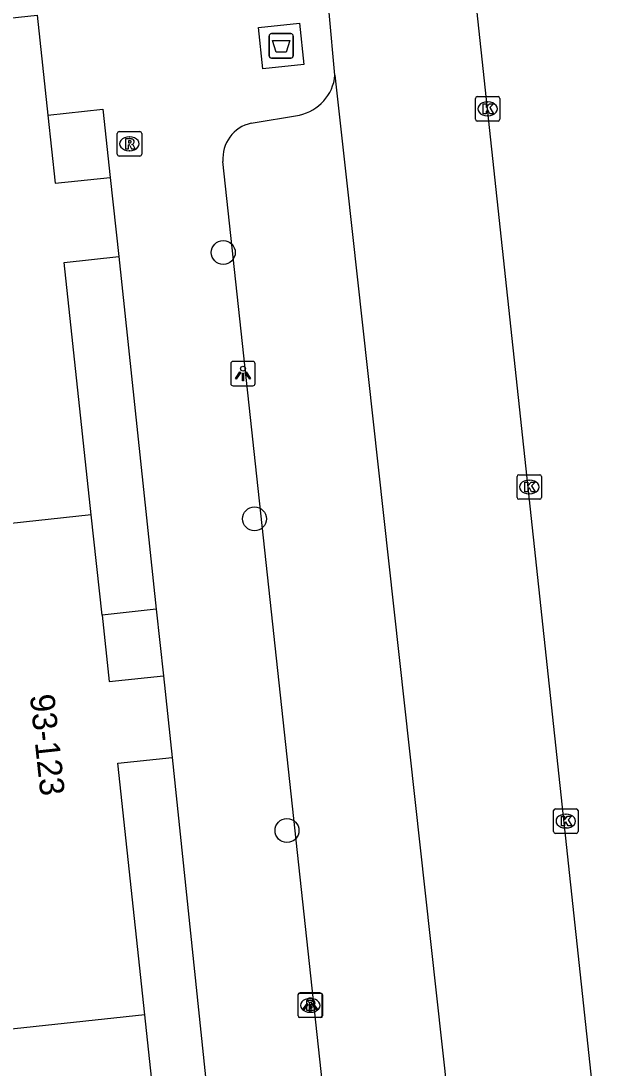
# Model space of a CAD drawing. Extents: x 161253 to 161848, y 384872 to 385383.
# Drawn here: x 161305.25 to 161328.98, y 385112.17 to 385154.91 of the extents above; entities that cross this region are included whole.
import ezdxf

# ---------------------------------------------------------------- set-up
doc = ezdxf.new("R2010")
doc.units = 0
for name, color, linetype in [('IMGEO_Afval_apart_plaats', 7, 'Continuous'), ('IMGEO_Boom', 7, 'Continuous'), ('IMGEO_Brandkraan', 7, 'Continuous'), ('IMGEO_Kolk', 7, 'Continuous'), ('IMGEO_Lichtpunt', 7, 'Continuous'), ('IMGEO_Pand', 7, 'Continuous'), ('IMGEO_Pand_nummerreeks', 7, 'Continuous'), ('IMGEO_Rijbaan_lokaal_open', 7, 'Continuous'), ('IMGEO_Rioolput', 7, 'Continuous'), ('IMGEO_Voetpad_gesloten', 7, 'Continuous'), ('IMGEO_Voetpad_open', 7, 'Continuous')]:
    doc.layers.add(name, color=color, linetype=linetype)

msp = doc.modelspace()

# ---------------------------------------------------------------- linework, layer by layer
at = {"layer": 'IMGEO_Afval_apart_plaats'}
for p, q in [((161315.384, 385153.496), (161315.384, 385154.296)), ((161315.384, 385154.296), (161315.384, 385153.496)), ((161315.484, 385154.396), (161316.274, 385154.396)), ((161316.274, 385154.396), (161315.484, 385154.396)), ((161316.374, 385154.296), (161316.374, 385153.496)), ((161316.374, 385153.496), (161316.374, 385154.296)), ((161316.274, 385153.396), (161315.484, 385153.396)), ((161315.484, 385153.396), (161316.274, 385153.396))]:
    msp.add_line(p, q, dxfattribs=at)
msp.add_lwpolyline([(161315.527, 385154.11), (161316.231, 385154.11), (161316.082, 385153.64), (161315.676, 385153.64), (161315.527, 385154.11)], dxfattribs=at)
for centre, start, end in [((161315.484, 385154.296), 90, 180), ((161315.484, 385154.296), 90, 180), ((161316.274, 385154.296), 0, 90), ((161316.274, 385154.296), 360, 90), ((161315.484, 385153.496), 180, 270), ((161315.484, 385153.496), 180, 270), ((161316.274, 385153.496), 270, 0), ((161316.274, 385153.496), 270, 0)]:
    msp.add_arc(centre, 0.1, start, end, dxfattribs=at)
at = {"layer": 'IMGEO_Boom'}
for centre in [(161313.513, 385145.462), (161314.788, 385134.591), (161316.115, 385121.867)]:
    msp.add_circle(centre, 0.489, dxfattribs=at)
at = {"layer": 'IMGEO_Brandkraan'}
for p, q in [((161316.566, 385114.305), (161316.566, 385115.157)), ((161316.641, 385115.231), (161317.493, 385115.231)), ((161317.567, 385115.157), (161317.567, 385114.305)), ((161317.054, 385115.011), (161317.079, 385115.011)), ((161317.077, 385114.451), (161317.052, 385114.451)), ((161317.493, 385114.231), (161316.641, 385114.231))]:
    msp.add_line(p, q, dxfattribs=at)
for points in [[(161316.566, 385114.305), (161316.566, 385115.157)], [(161316.641, 385115.231), (161317.493, 385115.231)], [(161317.567, 385115.157), (161317.567, 385114.305)], [(161316.914, 385114.931), (161316.914, 385114.531), (161317.127, 385114.531)], [(161317.145, 385114.931), (161316.914, 385114.931)], [(161317.093, 385114.85), (161317.039, 385114.85), (161317.039, 385114.774)], [(161317.039, 385114.774), (161317.092, 385114.774)], [(161317.101, 385114.698), (161317.039, 385114.698), (161317.039, 385114.617)], [(161317.039, 385114.617), (161317.101, 385114.617)], [(161317.493, 385114.231), (161316.641, 385114.231)]]:
    msp.add_lwpolyline(points, dxfattribs=at)
for centre, radius, start, end in [((161316.643, 385115.155), 0.0765, 91.552, 178.448), ((161316.643, 385115.155), 0.0765, 91.552, 178.448), ((161317.491, 385115.155), 0.0765, 1.552, 88.448), ((161317.491, 385115.155), 0.0765, 1.552, 88.448), ((161317.094, 385114.812), 0.0379, 267.8285, 90.9355), ((161317.149, 385114.786), 0.145, 59.4692, 91.5367), ((161317.174, 385114.833), 0.0922, 285.5137, 58.1501), ((161317.179, 385114.641), 0.105, 301.3115, 78.989), ((161316.643, 385114.307), 0.0765, 181.552, 268.448), ((161316.643, 385114.307), 0.0765, 181.552, 268.448), ((161317.102, 385114.657), 0.0404, 269.8759, 90.5077), ((161317.133, 385114.782), 0.251, 268.6676, 293.5347), ((161317.491, 385114.307), 0.0765, 271.552, 358.448), ((161317.491, 385114.307), 0.0765, 271.552, 358.448)]:
    msp.add_arc(centre, radius, start, end, dxfattribs=at)
for centre, major_axis, ratio, start_param, end_param in [((161317.053, 385114.731), (-0.387, 0.002), 0.722429, 4.712389, 7.853982), ((161317.078, 385114.731), (-0.39, 0.002), 0.717154, 1.570796, 4.712389)]:
    msp.add_ellipse(centre, major_axis=major_axis, ratio=ratio, start_param=start_param, end_param=end_param, dxfattribs=at)
at = {"layer": 'IMGEO_Kolk'}
for p, q in [((161323.809, 385150.9), (161323.809, 385151.752)), ((161323.884, 385151.826), (161324.736, 385151.826)), ((161324.297, 385151.606), (161324.322, 385151.606)), ((161324.81, 385151.752), (161324.81, 385150.9)), ((161324.32, 385151.046), (161324.295, 385151.046)), ((161324.736, 385150.826), (161323.884, 385150.826)), ((161325.511, 385135.466), (161325.511, 385136.318)), ((161325.586, 385136.392), (161326.438, 385136.392)), ((161325.999, 385136.172), (161326.024, 385136.172)), ((161326.512, 385136.318), (161326.512, 385135.466)), ((161326.438, 385135.392), (161325.586, 385135.392)), ((161326.022, 385135.612), (161325.997, 385135.612)), ((161327.003, 385121.828), (161327.003, 385122.68)), ((161327.078, 385122.754), (161327.93, 385122.754)), ((161327.491, 385122.534), (161327.516, 385122.534)), ((161328.004, 385122.68), (161328.004, 385121.828)), ((161327.93, 385121.754), (161327.078, 385121.754)), ((161327.514, 385121.974), (161327.489, 385121.974))]:
    msp.add_line(p, q, dxfattribs=at)
for points in [[(161323.809, 385150.9), (161323.809, 385151.752)], [(161323.884, 385151.826), (161324.736, 385151.826)], [(161324.13, 385151.526), (161324.253, 385151.526), (161324.253, 385151.375), (161324.383, 385151.526), (161324.547, 385151.526), (161324.401, 385151.375), (161324.554, 385151.126), (161324.402, 385151.126), (161324.317, 385151.29), (161324.253, 385151.223), (161324.253, 385151.126), (161324.13, 385151.126), (161324.13, 385151.526)], [(161324.81, 385151.752), (161324.81, 385150.9)], [(161324.736, 385150.826), (161323.884, 385150.826)], [(161325.511, 385135.466), (161325.511, 385136.318)], [(161325.586, 385136.392), (161326.438, 385136.392)], [(161325.832, 385136.092), (161325.955, 385136.092), (161325.955, 385135.941), (161326.085, 385136.092), (161326.249, 385136.092), (161326.103, 385135.941), (161326.256, 385135.692), (161326.104, 385135.692), (161326.019, 385135.856), (161325.955, 385135.789), (161325.955, 385135.692), (161325.832, 385135.692), (161325.832, 385136.092)], [(161326.512, 385136.318), (161326.512, 385135.466)], [(161326.438, 385135.392), (161325.586, 385135.392)], [(161327.003, 385121.828), (161327.003, 385122.68)], [(161327.078, 385122.754), (161327.93, 385122.754)], [(161327.324, 385122.454), (161327.447, 385122.454), (161327.447, 385122.303), (161327.577, 385122.454), (161327.741, 385122.454), (161327.595, 385122.303), (161327.748, 385122.054), (161327.596, 385122.054), (161327.511, 385122.218), (161327.447, 385122.151), (161327.447, 385122.054), (161327.324, 385122.054), (161327.324, 385122.454)], [(161328.004, 385122.68), (161328.004, 385121.828)], [(161327.93, 385121.754), (161327.078, 385121.754)]]:
    msp.add_lwpolyline(points, dxfattribs=at)
for centre, start, end in [((161323.886, 385151.75), 91.552, 178.448), ((161323.886, 385151.75), 91.552, 178.448), ((161324.734, 385151.75), 1.552, 88.448), ((161324.734, 385151.75), 1.552, 88.448), ((161323.886, 385150.902), 181.552, 268.448), ((161323.886, 385150.902), 181.552, 268.448), ((161324.734, 385150.902), 271.552, 358.448), ((161324.734, 385150.902), 271.552, 358.448), ((161325.588, 385136.316), 91.552, 178.448), ((161325.588, 385136.316), 91.552, 178.448), ((161326.436, 385136.316), 1.552, 88.448), ((161326.436, 385136.316), 1.552, 88.448), ((161325.588, 385135.468), 181.552, 268.448), ((161325.588, 385135.468), 181.552, 268.448), ((161326.436, 385135.468), 271.552, 358.448), ((161326.436, 385135.468), 271.552, 358.448), ((161327.08, 385122.678), 91.552, 178.448), ((161327.08, 385122.678), 91.552, 178.448), ((161327.928, 385122.678), 1.552, 88.448), ((161327.928, 385122.678), 1.552, 88.448), ((161327.08, 385121.83), 181.552, 268.448), ((161327.08, 385121.83), 181.552, 268.448), ((161327.928, 385121.83), 271.552, 358.448), ((161327.928, 385121.83), 271.552, 358.448)]:
    msp.add_arc(centre, 0.0765, start, end, dxfattribs=at)
for centre, major_axis, ratio, start_param, end_param in [((161324.296, 385151.326), (-0.387, 0.002), 0.722429, 4.712389, 7.853982), ((161324.321, 385151.326), (-0.39, 0.002), 0.717154, 1.570796, 4.712389), ((161325.998, 385135.892), (-0.387, 0.002), 0.722429, 4.712389, 7.853982), ((161326.023, 385135.892), (-0.39, 0.002), 0.717154, 1.570796, 4.712389), ((161327.49, 385122.254), (-0.387, 0.002), 0.722429, 4.712389, 7.853982), ((161327.515, 385122.254), (-0.39, 0.002), 0.717154, 1.570796, 4.712389)]:
    msp.add_ellipse(centre, major_axis=major_axis, ratio=ratio, start_param=start_param, end_param=end_param, dxfattribs=at)
at = {"layer": 'IMGEO_Lichtpunt'}
for p, q in [((161313.819, 385140.925), (161313.819, 385140.118)), ((161313.819, 385140.925), (161313.819, 385140.118)), ((161314.721, 385141.02), (161313.913, 385141.02)), ((161314.721, 385141.02), (161313.913, 385141.02)), ((161314.815, 385140.118), (161314.815, 385140.925)), ((161314.815, 385140.118), (161314.815, 385140.925)), ((161313.913, 385140.024), (161314.721, 385140.024)), ((161313.913, 385140.024), (161314.721, 385140.024)), ((161316.561, 385115.146), (161316.561, 385114.339)), ((161316.561, 385115.146), (161316.561, 385114.339)), ((161317.463, 385115.241), (161316.655, 385115.241)), ((161317.463, 385115.241), (161316.655, 385115.241)), ((161317.557, 385114.339), (161317.557, 385115.146)), ((161317.557, 385114.339), (161317.557, 385115.146)), ((161316.655, 385114.245), (161317.463, 385114.245)), ((161316.655, 385114.245), (161317.463, 385114.245))]:
    msp.add_line(p, q, dxfattribs=at)
for points in [[(161314.193, 385140.589), (161314.232, 385140.561), (161314.044, 385140.299), (161314.006, 385140.326), (161314.193, 385140.589)], [(161314.295, 385140.541), (161314.342, 385140.541), (161314.342, 385140.219), (161314.295, 385140.219), (161314.295, 385140.541)], [(161314.405, 385140.561), (161314.443, 385140.588), (161314.63, 385140.326), (161314.591, 385140.298), (161314.405, 385140.561)], [(161316.935, 385114.81), (161316.974, 385114.782), (161316.786, 385114.52), (161316.748, 385114.547), (161316.935, 385114.81)], [(161317.037, 385114.762), (161317.084, 385114.762), (161317.084, 385114.44), (161317.037, 385114.44), (161317.037, 385114.762)], [(161317.147, 385114.782), (161317.185, 385114.809), (161317.372, 385114.547), (161317.333, 385114.519), (161317.147, 385114.782)]]:
    msp.add_lwpolyline(points, dxfattribs=at)
for centre in [(161314.318, 385140.723), (161317.06, 385114.944)]:
    msp.add_circle(centre, 0.0994, dxfattribs=at)
for centre, start, end in [((161313.913, 385140.925), 90, 180), ((161313.913, 385140.925), 90, 180), ((161314.721, 385140.925), 0, 90), ((161314.721, 385140.925), 0, 90), ((161313.913, 385140.118), 180, 270), ((161313.913, 385140.118), 180, 270), ((161314.721, 385140.118), 270, 0), ((161314.721, 385140.118), 270, 360), ((161316.655, 385115.146), 90, 180), ((161316.655, 385115.146), 90, 180), ((161317.463, 385115.146), 0, 90), ((161317.463, 385115.146), 0, 90), ((161316.655, 385114.339), 180, 270), ((161316.655, 385114.339), 180, 270), ((161317.463, 385114.339), 270, 0), ((161317.463, 385114.339), 270, 360)]:
    msp.add_arc(centre, 0.0946, start, end, dxfattribs=at)
at = {"layer": 'IMGEO_Pand'}
for points in [[(161291.96, 385153.649), (161305.913, 385155.151), (161306.352, 385151.066)], [(161306.352, 385151.066), (161306.651, 385148.286), (161308.895, 385148.528)], [(161308.895, 385148.528), (161309.243, 385145.295)], [(161308.121, 385134.749), (161307.012, 385145.055), (161309.243, 385145.295)], [(161308.121, 385134.749), (161294.156, 385133.247)], [(161308.561, 385130.663), (161308.121, 385134.749)], [(161308.561, 385130.663), (161308.853, 385127.948), (161311.065, 385128.187)], [(161311.065, 385128.187), (161311.424, 385124.852)], [(161310.306, 385114.346), (161309.2, 385124.612), (161311.424, 385124.852)], [(161310.306, 385114.346), (161296.352, 385112.845)], [(161310.744, 385110.276), (161310.306, 385114.346)]]:
    msp.add_lwpolyline(points, dxfattribs=at)
at = {"layer": 'IMGEO_Rijbaan_lokaal_open'}
for points in [[(161323.818, 385155.771), (161332.231, 385077.462)], [(161318.074, 385152.697), (161317.833, 385155.253)], [(161318.074, 385152.697), (161318.555, 385148.292), (161321.975, 385117.333), (161325.055, 385089.483), (161326.877, 385072.057)]]:
    msp.add_lwpolyline(points, dxfattribs=at)
at = {"layer": 'IMGEO_Rioolput'}
for p, q in [((161309.18, 385149.472), (161309.18, 385150.324)), ((161309.255, 385150.398), (161310.107, 385150.398)), ((161310.181, 385150.324), (161310.181, 385149.472)), ((161309.668, 385150.178), (161309.693, 385150.178)), ((161310.107, 385149.398), (161309.255, 385149.398)), ((161309.691, 385149.618), (161309.666, 385149.618))]:
    msp.add_line(p, q, dxfattribs=at)
for points in [[(161309.18, 385149.472), (161309.18, 385150.324)], [(161309.255, 385150.398), (161310.107, 385150.398)], [(161310.181, 385150.324), (161310.181, 385149.472)], [(161309.769, 385150.096), (161309.517, 385150.098), (161309.517, 385149.698)], [(161309.517, 385149.698), (161309.641, 385149.698), (161309.641, 385149.86), (161309.652, 385149.86)], [(161309.695, 385150.017), (161309.641, 385150.017), (161309.641, 385149.936)], [(161309.641, 385149.936), (161309.693, 385149.936)], [(161309.699, 385149.831), (161309.77, 385149.698), (161309.91, 385149.698), (161309.845, 385149.824)], [(161310.107, 385149.398), (161309.255, 385149.398)]]:
    msp.add_lwpolyline(points, dxfattribs=at)
for centre, radius, start, end in [((161309.257, 385150.322), 0.0765, 91.552, 178.448), ((161309.257, 385150.322), 0.0765, 91.552, 178.448), ((161310.105, 385150.322), 0.0765, 1.552, 88.448), ((161310.105, 385150.322), 0.0765, 1.552, 88.448), ((161309.651, 385149.807), 0.0533, 26.0293, 88.6989), ((161309.677, 385150.125), 0.19, 274.7715, 282.9687), ((161309.701, 385149.921), 0.0964, 77.0061, 93.1865), ((161309.715, 385149.978), 0.0378, 276.6634, 79.6772), ((161309.768, 385149.986), 0.109, 350.3612, 89.416), ((161309.766, 385149.986), 0.112, 277.5842, 350.9817), ((161309.75, 385149.771), 0.108, 29.5134, 73.7905), ((161309.257, 385149.474), 0.0765, 181.552, 268.448), ((161309.257, 385149.474), 0.0765, 181.552, 268.448), ((161310.105, 385149.474), 0.0765, 271.552, 358.448), ((161310.105, 385149.474), 0.0765, 271.552, 358.448)]:
    msp.add_arc(centre, radius, start, end, dxfattribs=at)
for centre, major_axis, ratio, start_param, end_param in [((161309.667, 385149.898), (-0.387, 0.002), 0.722429, 4.712389, 7.853982), ((161309.692, 385149.898), (-0.39, 0.002), 0.717154, 1.570796, 4.712389)]:
    msp.add_ellipse(centre, major_axis=major_axis, ratio=ratio, start_param=start_param, end_param=end_param, dxfattribs=at)
at = {"layer": 'IMGEO_Voetpad_gesloten'}
msp.add_lwpolyline([(161315.126, 385152.965), (161314.948, 385154.648), (161316.631, 385154.826), (161316.809, 385153.143), (161315.126, 385152.965)], dxfattribs=at)
at = {"layer": 'IMGEO_Voetpad_open'}
for points in [[(161306.352, 385151.066), (161308.596, 385151.307), (161308.895, 385148.528)], [(161314.656, 385150.742), (161316.623, 385151.075)], [(161326.412, 385072.422), (161321.861, 385071.864), (161313.501, 385149.174)], [(161309.243, 385145.295), (161310.773, 385130.901)], [(161310.773, 385130.901), (161308.561, 385130.663)], [(161310.773, 385130.901), (161311.065, 385128.187)], [(161311.424, 385124.852), (161312.921, 385110.511)]]:
    msp.add_lwpolyline(points, dxfattribs=at)
for centre, radius, start, end in [((161316.249, 385152.87), 1.834, 281.7832, 354.5868), ((161314.971, 385149.3), 1.476, 102.3347, 184.914)]:
    msp.add_arc(centre, radius, start, end, dxfattribs=at)

# ---------------------------------------------------------------- texts
at = {"layer": 'IMGEO_Pand_nummerreeks'}
msp.add_text('93-123', height=1, rotation=276.1132, dxfattribs=at).set_placement((161305.611, 385127.387))

doc.saveas('drawing.dxf')
